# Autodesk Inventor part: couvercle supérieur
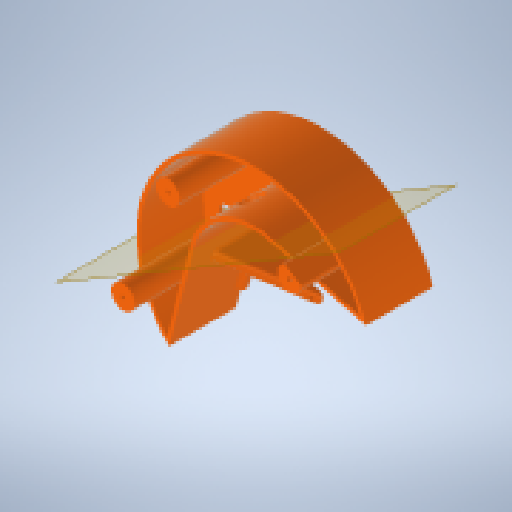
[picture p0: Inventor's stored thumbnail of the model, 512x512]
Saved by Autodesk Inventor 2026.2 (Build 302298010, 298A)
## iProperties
Created: 2026-09
Part Number: couvercle supérieur
Material: Plastique ABS
Document SubType Name: Modeling
Designer: mel
Density: 1.06 g/cm^3
Appearance: Lisse - Orange clair
Mass: 68.7124 g
Surface Area: 537.175 cm^2
Volume: 68.7124 cm^3
Author: mel
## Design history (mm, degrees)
sketch "Esquisse1"
  geometry: L1 (11.529, 26.733)-(73.285, 10.893) reference; L2 (-52.387, -63.471)-(-36.547, -1.715) reference; A1 r 75 centre (1.715, -11.529) between (73.285, 10.893) and (-52.387, -63.471) reference; A2 r 39.5 centre (1.715, -11.529) between (11.529, 26.733) and (-36.547, -1.715) reference; 1 further point
extrude "Extrusion1" new body sketch "Esquisse1" distance "d0" = 42.75; taper "d1" = 0 deg
feature "Coque1" dims "d2" = 2.5
sketch "Esquisse2"
  geometry: L1 (-11.529, 26.733)-(-73.285, 10.893) reference; L2 (52.387, -63.471)-(36.547, -1.715) reference; L3 (-23.33, 20.609)-(-62.379, 10.593); L4 (48.658, -48.935)-(45.752, -49.68); L5 (-62.379, 10.593)-(-63.125, 13.499); L6 (2.567, 24.719)-(2.919, 27.698); L7 (-23.33, 20.609)-(-24.075, 23.515); L8 (39.911, -26.906)-(42.817, -26.161); L9 (35.441, -9.479)-(38.969, -8.574); L10 (45.752, -49.68)-(39.911, -26.906); L11 (35.441, -9.479)-(33.641, -2.46); A1 r 39.5 centre (-1.715, -11.529) between (36.547, -1.715) and (-11.529, 26.733) reference; A2 r 36.5 centre (-1.715, -11.529) between (33.641, -2.46) and (2.567, 24.719); 2 further points
  constraints: 18 end point, 7 perpendicular, 4 point on line, 3 point on circle, 1 centre point, 1 line through centre
extrude "Extrusion2" join sketch "Esquisse2" stored distance "d4" = 6; taper "d5" = 0 deg
fillet "Congé1" dims "d6" = 2
sketch "Esquisse3"
  geometry: L1 (-73.655, 4.75)-(-73.655, 27.75) reference; L2 (-53.855, 27.75)-(-53.855, 4.75) reference; L3 (-54.755, 0.75)-(-72.755, 0.75) reference; L4 (-73.655, 5.866)-(-53.855, 5.866); L5 (-53.855, 5.866)-(-53.855, 0.75); L6 (-53.855, 0.75)-(-73.655, 0.75); L7 (-73.655, 0.75)-(-73.655, 5.866); 6 further points
  constraints: 8 end point, 2 parallel, 1 horizontal, 1 perpendicular, 1 point on line
  node "Référence7"
  node "Référence8"
  node "Référence9"
node "Plan de construction1"
extrude "Extrusion3" join sketch "Esquisse3" distance "d7" = 9; taper "d8" = 0 deg
sketch "Esquisse4"
  geometry: C1 r 2 at (4.9, -5.64) reference; C2 r 2 at (14.9, -5.64) reference; C3 r 1.25 at (4.9, -5.64); C4 r 1.25 at (14.9, -5.64); 1 further point
  constraints: 2 centre point, 2 coincident
  dimensions: "d9" = 2.5 diameter of C3 (= d10); "d10" = 2.5 diameter of C4
extrude "Extrusion4" cut sketch "Esquisse4" extent not by distance; stored distance "d11" = 0; taper "d12" = 0 deg
sketch "Esquisse5"
  geometry: L1 (42, 46.115)-(42, 53.615) reference; L2 (36.884, 103.255)-(36.884, 94.255) reference; L3 (36.884, 93.615)-(36.884, 34.291); L4 (42, 46.115)-(37, 46.115); L5 (37, 46.115)-(37, 52.68); L6 (37, 52.68)-(42, 52.68); L7 (42, 52.68)-(42, 46.115); 2 further points
  constraints: 10 end point, 2 parallel, 1 horizontal, 1 perpendicular, 1 vertical
  dimensions: "d13" = 5 distance of L5.end L6.end
  node "Référence12"
node "Plan de construction2"
extrude "Extrusion5" join sketch "Esquisse5" stored distance "d14" = 10; taper "d15" = 0 deg
sketch "Esquisse6"
  geometry: L1 (48.5, 0)-(48.5, 5) reference; L2 (48.5, 5)-(0, 26.267); L3 (0, -0.75)-(0, 42) reference; L4 (0, 5)-(48.5, 5) reference; L5 (48.5, 5)-(0, 5); L6 (0, 5)-(0, 26.267); 1 further point
  constraints: 6 end point, 1 collinear, 1 perpendicular, 1 point on line
extrude "Extrusion6" join sketch "Esquisse6" stored distance "d16" = 10; taper "d17" = 0 deg
fillet "Congé2" dims "d18" = 2
sketch "Esquisse7"
  geometry: C1 r 2 at (-44.5, 5.5) reference; C2 r 2 at (-34.5, 5.5) reference; C3 r 1.25 at (-44.5, 5.5); C4 r 1.25 at (-34.5, 5.5); 1 further point
  constraints: 2 centre point, 2 coincident
  dimensions: "d19" = 2.5 diameter of C3; "d20" = 2.5 diameter of C4
extrude "Extrusion7" cut sketch "Esquisse7" extent not by distance; stored distance "d21" = 0; taper "d22" = 0 deg
sketch "Esquisse8"
  geometry: C1 r 7.5 at (61.64, 16.633); A1 r 36.5 centre (0, 0) between (14.774, 33.376) and (-25.809, 25.809) reference; 2 further points
  constraints: 1 centre point, 1 coincident
  dimensions: "d23" = 15 diameter of C1
node "Plan de construction3"
node "Plan de construction4"
extrude "Extrusion8" join sketch "Esquisse8" stored distance "d24" = 10; taper "d25" = 0 deg
sketch "Esquisse9"
  geometry: C1 r 7.5 at (0, 0) reference; 1 further point
hole "Perçage1" sketch "Esquisse9" at (0, 0) diameter "d26" = 2.5; stored, may be unused: countersink angle "d30" = 90 deg, drill point angle "d32" = 118 deg; dims "d27" = 6, "d28" = 4, "d29" = 2, "d31" = 12
pattern_circular "Réseau circulaire1" dims "d34" = 150 deg
sketch "Esquisse10"
  geometry: A1 r 39.5 centre (0, 0) between (27.931, 27.931) and (-27.931, 27.931) reference; 2 further points
  dimensions: "d46" = 65 distance of point (64.949, 2.57) A1.centre
hole "Perçage2" sketch "Esquisse10" at (64.949, 2.57) diameter "d36" = 2.5; stored, may be unused: countersink angle "d40" = 90 deg, drill point angle "d42" = 118 deg; dims "d37" = 6, "d38" = 4, "d39" = 2, "d41" = 12
pattern_circular "Réseau circulaire2" dims angle "d44" = 175 deg
sketch "Esquisse11"
  geometry: L1 (28.5, 3)-(46.5, 3) reference; L2 (0, 0)-(44.5, 0) reference; L3 (28.5, 3)-(25.5, 3); L4 (25.5, 3)-(25.5, 0); L5 (25.5, 0)-(28.5, 0); L6 (28.5, 0)-(28.5, 3); L7 (46.5, 3)-(46.5, 0); L8 (46.5, 0)-(25.5, 0); 2 further points
  constraints: 12 end point, 2 parallel, 1 collinear, 1 horizontal, 1 perpendicular, 1 point on line, 1 vertical
  dimensions: "d47" = 3 distance between parallel lines of L4 L6
extrude "Extrusion9" cut sketch "Esquisse11" stored distance "d48" = 0; taper "d49" = 0 deg
sketch "Esquisse12"
  geometry: L1 (-72.755, 3.75)-(-54.755, 3.75) reference; L2 (-54.755, 1.25)-(-54.755, 3.75) reference; L3 (-54.755, 3.75)-(-52.041, 3.75); L4 (-52.041, 3.75)-(-52.041, 0.73); L5 (-52.041, 0.73)-(-54.755, 0.73); L6 (-54.755, 0.73)-(-54.755, 3.75); 2 further points
  constraints: 8 end point, 2 parallel, 1 horizontal, 1 perpendicular
extrude "Extrusion10" cut sketch "Esquisse12" stored distance "d50" = 10; taper "d51" = 0 deg
sketch "Esquisse13"
  geometry: L1 (-9.9, -1.261)-(-9.9, -9) reference; L2 (9.9, -9)-(-9.9, -9) reference; L3 (9.9, 0)-(9.9, -9) reference; L4 (0, 0)-(9.9, 0) reference; C1 r 1.25 at (-5, -5.64) reference; C2 r 1.25 at (5, -5.64) reference; A1 r 39.5 centre (0, -39.5) between (0, 0) and (-9.9, -1.261) reference; 1 further point
extrude "Extrusion11" join sketch "Esquisse13" distance "d52" = 5; taper "d53" = 0 deg
node "Plan de construction5"
sketch "Esquisse14"
  geometry: C1 r 7.5 at (21.736, 26.862); 1 further point
  constraints: 1 centre point
  dimensions: "d54" = 15 diameter of C1
extrude "Extrusion12" cut sketch "Esquisse14" distance "d55" = 25; taper "d56" = 0 deg
sketch "Esquisse15"
  geometry: L1 (-0.25, 36.095)-(-0.25, 37.345) reference; L2 (-0.25, 37.345)-(-4.25, 37.345) reference; L3 (-4.25, 37.345)-(-4.25, 50.845) reference; L4 (-4.25, 50.845)-(-0.25, 50.845) reference; L5 (-0.25, 50.845)-(-0.25, 52.095) reference; L6 (-2.75, 54.595)-(-21.75, 54.595) reference; L7 (-24.25, 52.095)-(-24.25, 36.095) reference; L8 (-21.75, 33.595)-(-2.75, 33.595) reference; L9 (-19.59, 47.172)-(-19.302, 47.172) reference; L10 (-19.302, 47.172)-(-19.302, 45.922) reference; L11 (-19.302, 45.922)-(-19.587, 45.922) reference; L12 (-17.941, 46.007)-(-17.941, 46.207) reference; L13 (-17.941, 46.207)-(-17.926, 46.207) reference; L14 (-17.782, 47.011)-(-17.782, 46.688) reference; L15 (-17.782, 46.688)-(-17.492, 46.688) reference; L16 (-17.492, 46.688)-(-17.492, 46.542) reference; L17 (-17.492, 46.542)-(-17.946, 46.542) reference; L18 (-17.946, 46.542)-(-17.946, 47.088) reference; L19 (-18.91, 43.505)-(-18.91, 43.705) reference; L20 (-18.91, 43.705)-(-18.897, 43.705) reference; L21 (-18.898, 44.388)-(-18.91, 44.388) reference; L22 (-18.91, 44.388)-(-18.91, 44.586) reference; L23 (-19.642, 41.069)-(-19.223, 41.069) reference; L24 (-19.223, 41.069)-(-19.223, 40.922) reference; L25 (-19.223, 40.922)-(-20.228, 40.922) reference; L26 (-20.228, 40.922)-(-20.228, 41.069) reference; L27 (-20.228, 41.069)-(-19.809, 41.069) reference; L28 (-19.809, 41.069)-(-19.809, 42.172) reference; L29 (-19.809, 42.172)-(-19.642, 42.172) reference; L30 (-19.642, 42.172)-(-19.642, 41.069) reference; L31 (-17.75, 53.095)-(-17.25, 53.595) reference; L32 (-17.25, 53.595)-(-9.75, 53.595) reference; L33 (-9.75, 53.595)-(-9.75, 51.595) reference; L34 (-9.75, 51.595)-(-10.25, 51.095) reference; L35 (-10.25, 51.095)-(-17.75, 51.095) reference; L36 (-17.75, 51.095)-(-17.75, 53.095) reference; L37 (-18.208, 41.702)-(-18.208, 40.922) reference; L38 (-18.208, 40.922)-(-18.374, 40.922) reference; L39 (-18.374, 40.922)-(-18.374, 41.702) reference; L40 (-18.947, 41.706)-(-18.947, 40.922) reference; L41 (-18.947, 40.922)-(-19.113, 40.922) reference; L42 (-19.113, 40.922)-(-19.113, 41.702) reference; L43 (-17.483, 44.672)-(-17.303, 44.672) reference; L44 (-17.303, 44.672)-(-16.873, 43.422) reference; L45 (-16.873, 43.422)-(-17.051, 43.422) reference; L46 (-17.051, 43.422)-(-17.398, 44.46) reference; L47 (-17.398, 44.46)-(-17.744, 43.422) reference; L48 (-17.744, 43.422)-(-17.913, 43.422) reference; L49 (-17.913, 43.422)-(-17.483, 44.672) reference; L50 (-19.942, 43.505)-(-19.942, 43.705) reference; L51 (-19.942, 43.705)-(-19.929, 43.705) reference; L52 (-19.93, 44.388)-(-19.942, 44.388) reference; L53 (-19.942, 44.388)-(-19.942, 44.586) reference; L54 (-18.862, 47.172)-(-18.309, 46.094) reference; L55 (-18.309, 46.094)-(-18.309, 47.172) reference; L56 (-18.309, 47.172)-(-18.154, 47.172) reference; L57 (-18.154, 47.172)-(-18.154, 45.922) reference; L58 (-18.154, 45.922)-(-18.39, 45.922) reference; L59 (-18.39, 45.922)-(-18.894, 46.911) reference; L60 (-18.894, 46.911)-(-18.894, 45.922) reference; L61 (-18.894, 45.922)-(-19.049, 45.922) reference; L62 (-19.049, 45.922)-(-19.049, 47.172) reference; L63 (-19.049, 47.172)-(-18.862, 47.172) reference; L64 (66, 101.345)-(64.75, 101.345) reference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; C1 r 0.5 at (-6.25, 49.595) reference; C2 r 0.5 at (-6.25, 38.595) reference; C3 r 0.5 at (-6.25, 44.095) reference; C4 r 0.5 at (-22.25, 41.555) reference; C5 r 1.5 at (-21.25, 51.595) reference; C6 r 1.5 at (-21.25, 36.595) reference; C7 r 0.5 at (-22.25, 46.635) reference; C8 r 0.5 at (-22.25, 44.095) reference; C9 r 0.5 at (52.5, 107.345) reference; C10 r 0.5 at (63.5, 107.345) reference; C11 r 0.5 at (58, 107.345) reference; C12 r 0.5 at (60.54, 123.345) reference; C13 r 1.5 at (50.5, 122.345) reference; C14 r 1.5 at (65.5, 122.345) reference; C15 r 0.5 at (55.46, 123.345) reference; C16 r 0.5 at (58, 123.345) reference; C17 r 5 at (58, 113.634); C18 r 5 at (-13.647, 44.095); A1 r 2.5 centre (-2.75, 52.095) between (-0.25, 52.095) and (-2.75, 54.595) reference; A2 r 2.5 centre (-21.75, 52.095) between (-21.75, 54.595) and (-24.25, 52.095) reference; A3 r 2.5 centre (-21.75, 36.095) between (-24.25, 36.095) and (-21.75, 33.595) reference; A4 r 2.5 centre (-2.75, 36.095) between (-2.75, 33.595) and (-0.25, 36.095) reference; A5 r 2.5 centre (66, 103.845) between (66, 101.345) and (68.5, 103.845) reference; A6 r 2.5 centre (66, 122.845) between (68.5, 122.845) and (66, 125.345) reference; A7 r 2.5 centre (50, 122.845) between (50, 125.345) and (47.5, 122.845) reference; A8 r 2.5 centre (50, 103.845) between (47.5, 103.845) and (50, 101.345) reference; 58 further points
  constraints: 2 centre point
  dimensions: "d57" = 10 diameter of C17; "d58" = 10 diameter of C18
extrude "Extrusion13" cut sketch "Esquisse15" distance "d59" = 5; taper "d60" = 0 deg
sketch "Esquisse16"
  geometry: L1 (-2.848, 6.938)-(7.5, 0); A1 r 7.5 centre (0, 0) between (-2.848, 6.938) and (7.5, 0) reference; 1 further point
  constraints: 2 end point, 2 point on circle
extrude "Extrusion14" cut sketch "Esquisse16" stored distance "d61" = 5; taper "d62" = 0 deg
node "Solide1"
node "Référence1"
node "Référence2"
node "Référence3"
node "Référence4"
node "Référence5"
node "Référence6"
node "Référence10"
node "Référence11"
node "Référence13"
node "Référence14"
node "Référence15"
node "Référence16"
node "Référence17"
node "Boucle projetée1"
node "Référence18"
node "Référence19"
other parameters: "d3" = 3
